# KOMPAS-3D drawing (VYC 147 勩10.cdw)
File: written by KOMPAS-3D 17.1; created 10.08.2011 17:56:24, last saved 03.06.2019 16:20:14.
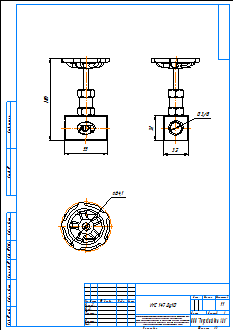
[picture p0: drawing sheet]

Sheet 1: A3, portrait

Title block, sheet 1: name: VYC 147 Ду10; material: Внимание! Данный продукт является объектом авторского права ООО «Торговый Дом АДЛ». / Запрещается изменение, копирование, распространение / (в том числе путем копирования на другие сайты и ресурсы в Интернете) / или любое иное использование информации и объектов без предварительного / согласия правообладателя (ООО «Торговый Дом АДЛ»).; scale: 1:1; sheets: 1; organisation: ООО "Торговый дом АДЛ"; sheet format: A3; stored path: \\adlc.lan\data\АДЛ_ПКД\3D-модели\Поставщики\VYC Industrial\VYC 147\KOMPAS 2D\VYC 147 Ду10.cdw

Views: Спереди 1, Проекционный вид 2, Проекционный вид 3
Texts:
  bsv
  adl
Dimensions and other numbers on the sheet: 55; 105; 32; 3/8; 64,1; 1:1; 1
